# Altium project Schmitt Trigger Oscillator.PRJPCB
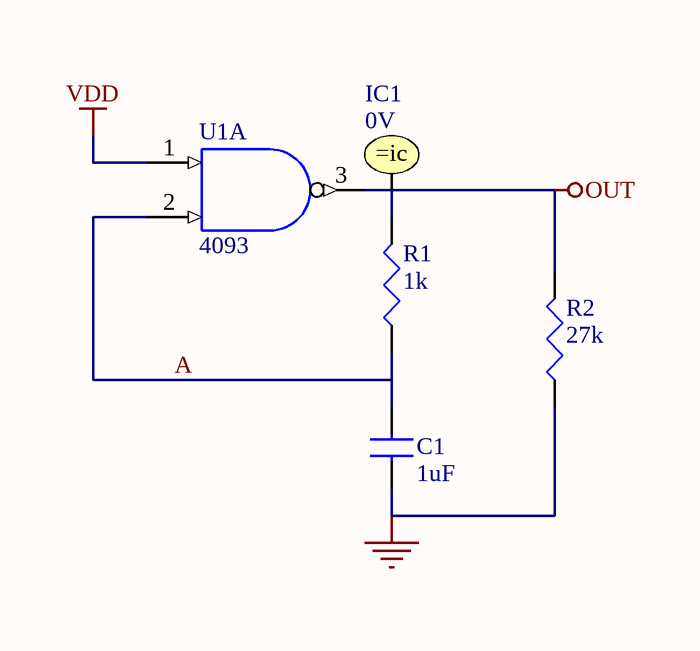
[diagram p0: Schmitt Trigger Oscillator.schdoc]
1 sheet, 5 parts. Net scope: global (net labels, ports and power ports of the same name join across sheets).

## Sheet Schmitt Trigger Oscillator.schdoc: Schmitt Trigger Oscillator
size A4; Organization: Altium Limited; Address1: L3, 12a Rodborough Rd; Address2: Frenchs Forest; Address3: NSW; Address4: Australia 2086; DocumentNumber: 1; SheetNumber: 1; SheetTotal: 1

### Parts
C1  1uF
IC1  Initial Voltage: 0V
R1  1k
R2  27k
U1  4093  (part A of 4)

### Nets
GND: C1.2 R2.2(BOT) U1.7(GND)
OUT: IC1.1 R1.1(TOP) R2.1(TOP) U1.3(1Y)
VDD: U1.1(1A) U1.14(VDD)
A: C1.1 R1.2(BOT) U1.2(1B)

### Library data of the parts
C1 = CAP: Capacitor
IC1 = .IC: Initial Condition
R1 R2 = RES: Resistor
U1 = 4093: Quad 2-Input NAND Schmitt-Trigger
